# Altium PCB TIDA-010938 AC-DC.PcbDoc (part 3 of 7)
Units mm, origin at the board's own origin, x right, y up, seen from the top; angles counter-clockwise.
Board outline 275 x 170 mm, 4 copper layers (Top Layer, Layer 1, Layer 2, Bottom Layer), stack 1.787 mm thick; 711 components, 426 nets, 2196 pads, 1444 vias.
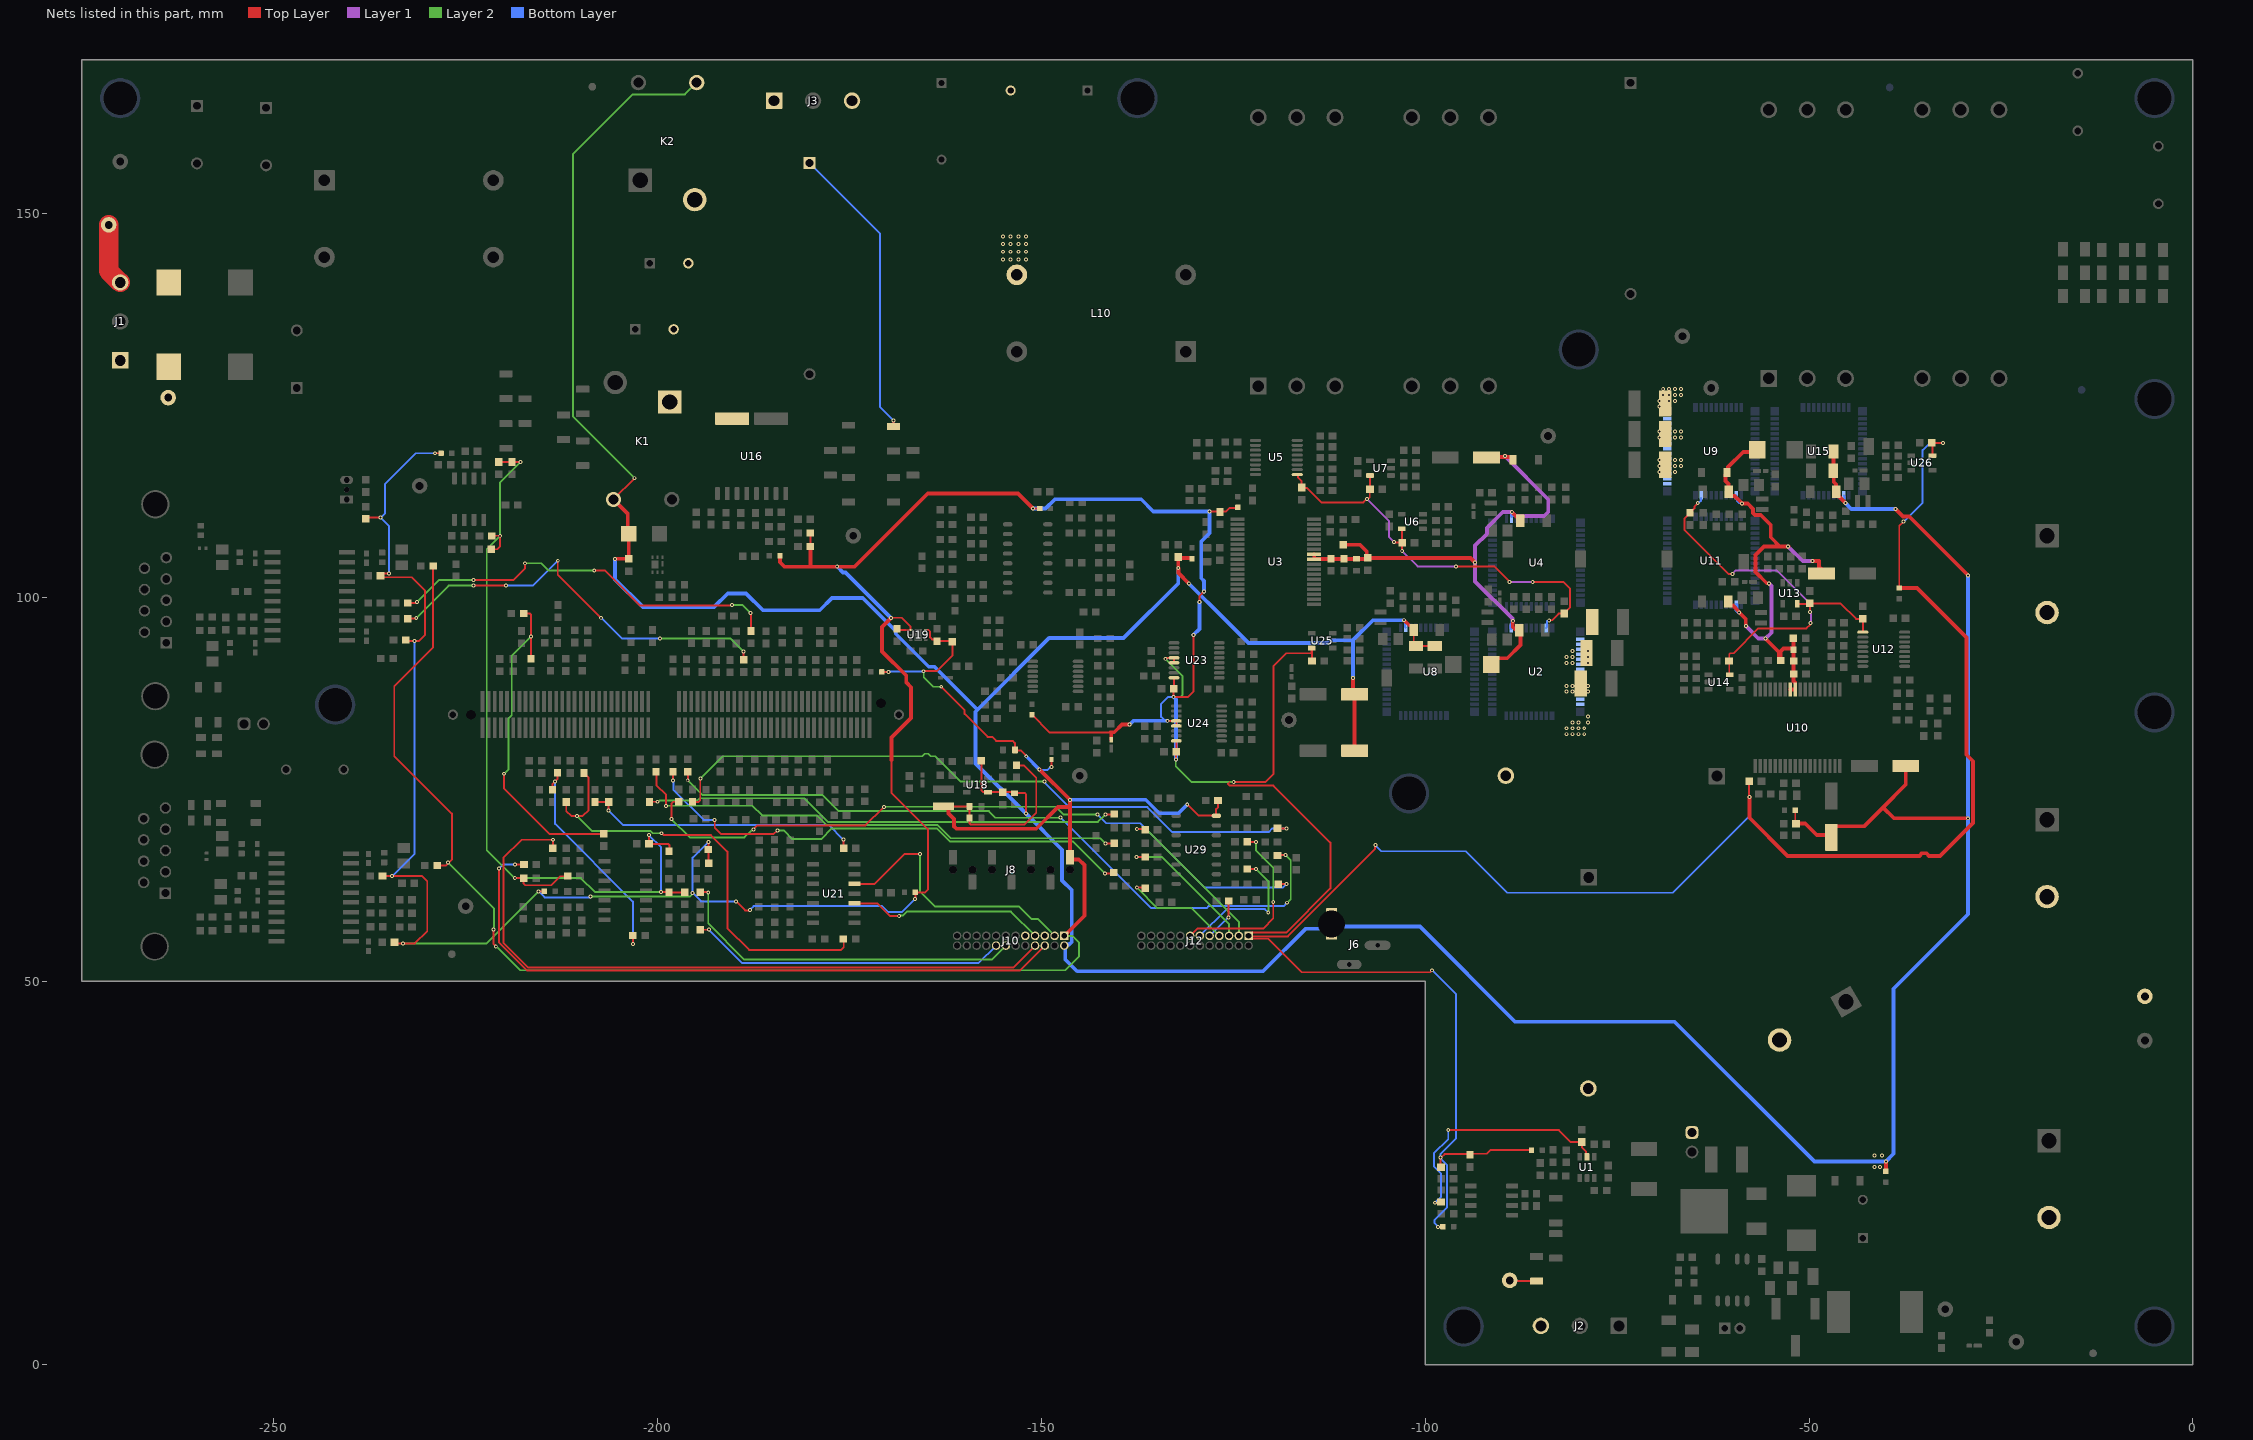
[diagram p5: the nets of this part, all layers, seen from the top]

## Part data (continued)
J6: library part CMP-0040211-1, "Power Barrel Connector Jack 2.10mm ID (0.083\"), 5.50mm OD (0.217\") Through Hole", Current_A=3A, Digikey Part Number=732-5931-ND, Manufacturer="Wurth Electronics", Mouser Part Number=710-694106402002, Operating Temperature Range="-40°C to +85°C", Voltage_V=30V
J7 J16: library part CMP-0054794-2, "Header, 2.54 mm, 2x1, Gold, TH", Color=Black, Manufacturer="Wurth Elektronik", Supplier Part Number 1=732-5315-ND
J8: library part CMP-0095208-1, "7 Position Receptacle, Bottom Entry Connector 0.100\" (2.54mm) Surface Mount Gold", Current_A=5.2A, Digikey Part Number=SSM-107-L-SV-BE-ND, Manufacturer=Samtec, Mouser Part Number=200-SSM107LSVBE, Operating Temperature Range="-55°C to +125°C", Voltage_V=572V
J10 J12: library part CMP-0003796-1, "Conn Shrouded Header (4 Sides) HDR 24 POS 1.27mm Solder ST Top Entry Thru-Hole Tube", Digikey Part Number=SHF-112-01-L-D-TH-ND, Manufacturer=Samtec, Mouser Part Number=200-SHF11201LDTH, Operating Temperature Range="-55°C to +125°C"
J11: library part CMP-0003814-2, "C2000 controlCARD-120HSEC connector, SMT", Manufacturer=Samtec
J15 J17: library part CMP-0054820-2, "Receptacle, D-Sub, 9 Position, R/A, TH", Color=Black, Current_A=3A, Manufacturer="Wurth Elektronik", Supplier Part Number 1=16T0655, Voltage_V=125V
K1 K2: library part CMP-0042926-1, "General Purpose Relay SPST-NO (1 Form A) 12VDC Coil Through Hole", Coil Power_W=450mW, Coil Resistance=320Ω, Coil Voltage_VDC=12V, Contact Rating_A=16A, Digikey Part Number=41-OJS-SH-112HEF,00000-ND, Manufacturer="TE Connectivity", Mouser Part Number=655-2071556-3, Operating Temperature Range=to
L1 L4: library part CMP-0048794-1, "Inductor 95.16 µH", Manufacturer=Bourns, Operating Temperature Range="-40°C to +125°C", Test Frequency=100Hz
L2 L3 L5 L6 L7 L9: library part CMP-0089347-1, "4.7µH Unshielded Inductor 1.1A 426mOhm Max 0806 (2016 Metric)", Digikey Part Number=2037-SDEM20161T-4R7MSCT-ND, Manufacturer=Cyntec, Operating Temperature Range="-55°C to +125°C", Test Frequency=1MHz, Tolerance_%=20%
L8 L12 L16 L17: library part CMP-0003349-2, "Ferrite Bead, 1500 ohm @ 100 MHz, 0.5 A, 0603", Manufacturer=MuRata, Supplier Part Number 1=490-5216-1-ND, Value1="0.5 ohm", Value2=0.5A, ValueDisplayed="1500 ohm"
L10 L11: library part CMP-0042320-3, "Common Mode Chokes 4mH 50mohm 250kHz", Manufacturer=Bourns, Operating Temperature Range="-40°C to +125°C", Test Frequency=250kHz
L13: library part CMP-0061866-2, "Inductor, Shielded, Ferrite, 220 uH, 2.1 A, 0.216 ohm, SMD", Manufacturer=Coilcraft, Supplier Part Number 1=994-MSS1210-224KEB, Value1="0.216 ohm", Value2=2.1A, ValueDisplayed=220uH
L14: library part CMP-0056744-1, "Inductor, Drum Core, Ferrite, 10 uH, 0.88 A, 0.276 ohm, SMD", Manufacturer=Bourns, Supplier Part Number 1=SRN3015-100MCT-ND, Value1="0.276 ohm", Value2=0.88A, ValueDisplayed=10uH
L25 L31: library part CMP-0084086-1, "100µH @ 100kHz 2 Line Common Mode Choke Surface Mount 5.8 kOhms @ 10MHz 150mA DCR 2Ohm", Digikey Part Number=445-3959-1-ND, Impedance At Frequency="5800Ω @ 10MHz", Manufacturer=TDK, Mouser Part Number=810-ACT45B1012PTL003, Operating Temperature Range="-40°C to +150°C", Test Frequency=100kHz, Tolerance_%=+50/-30%
LBL1: library part CMP-0003625-1, "Thermal Transfer Printable Labels, 0.650\" W x 0.200\" H - 10,000 per roll", Manufacturer=Brady, Supplier Part Number 1=97C5133
LOGO1: library part CMP-0074837-1, "IEC 61010-1 Hot Surface Warning"
LOGO2: library part CMP-0074835-1, "IEC 61010-1 High Voltage Warning"
Logo3: library part CMP-0074844-1
Logo5: library part CMP-0074847-1, "FCC_disclaimer"
Logo6: library part CMP-0074769-1
MP1 MP2 MP3 MP5 MP6 MP7 MP8 MP9 MP10 MP12: library part CMP-0040203-1, "Round Spacer Unthreaded Steel 0.059\" (1.50mm)", Digikey Part Number=732-7071-1-ND, Manufacturer="Wurth Electronics", Mouser Part Number=710-9774015960R, Operating Temperature Range="-55°C to +150°C"
Q1: library part CMP-0076725-1, "30-V N-Channel NexFET™ Power MOSFET", Manufacturer="Texas Instruments"
Q2: library part CMP-0001278-3, "MOSFET, N-CH, 800 V, 2.5 A, DPAK", Alternate Manufacturer=None, Manufacturer=STMicroelectronics, Supplier Part Number 1=497-7968-1-ND, Value2="19 nC"
R1: library part CMP-0084746-1, "RES, 0.001, 1%, 5 W, AEC-Q200 Grade 0, 6.35x3.05mm", Manufacturer=Bourns, Power_W=5W, TempCo="75 ppm/C", Tolerance_%=1%, Value_Code=1L000, ValueDisplayed=0.001
R2 R8 R9 R18 R19 R20 R22 R24 R25 R26 R27 R28 R29 R31 R32 R35 R37 R38 R39 R54 R56 R58 R59 R61 R62 R63 R64 R65 R66 R67 R68 R69 R71 R72 R73 R83 R86 R87 R88 R120 R121 R134 R140 R141 R150 R151 R160 R161 R169 R170 R238 R239 R257 R259 R260 R263 R264 R265 R267 R268 R269 R270 R272 R273 R274 R276 R278 R279 R281 R282 R284 R286 R311 R314 R319 R320 R323: library part CMP-0023572-3, "RES, 56, 0.1%, 0.1 W, 0603", Manufacturer="Susumu Co Ltd", Power_W=100mW, Supplier Part Number 1=RG16P56.0BCT-ND, TempCo="25 ppm/C", Tolerance_%=0.1%, Value2=0.1W, Value_Code=56R0, ValueDisplayed=56
R3 R4: library part CMP-0023661-3, "RES, 10.0, 0.1%, 0.1 W, 0603", Manufacturer="Yageo America", Power_W=100mW, TempCo="25 ppm/C", Tolerance_%=0.1%, Value2=0.1W, Value_Code=10R0, ValueDisplayed=10.0
R5 R33 R34 R50 R99 R108 R109 R110 R125 R126 R130 R131 R133 R135 R147 R149 R153 R155 R157 R158 R162 R164 R166 R167 R168 R171 R172 R173 R237 R252 R253 R254 R255 R256 R258 R297 R298 R299 R300 R301 R302 R303 R304 R305 R306 R307 R308 R310 R318 R328 R329 R330 R331 R332 R335 R336 R337 R338: library part CMP-0023404-3, "RES, 10.0 k, 0.1%, 0.1 W, 0603", Manufacturer="Susumu Co Ltd", Power_W=100mW, Supplier Part Number 1=RG16P10.0KBCT-ND, TempCo="25 ppm/C", Tolerance_%=0.1%, Value2=0.1W, Value_Code=10k0, ValueDisplayed=10.0k
R6: library part CMP-0089579-1, "SENSOR PTC 10K OHM 1% TO92S", Digikey Part Number=296-TMP6131LPGMCT-ND, Manufacturer="Texas Instruments", Max Current=400uA, Mouser Part Number=595-TMP6131LPGM, Operating Temperature Range="-40°C to +150°C", TempCo=6400ppm/°C, Tolerance_%=1%
R7 R41 R53 R55: library part CMP-0018694-3, "RES, 4.7, 5%, 0.75 W, AEC-Q200 Grade 0, 1206", Manufacturer=Vishay-Dale, Power_W=750mW, Supplier Part Number 1=541-4.7UACT-ND, TempCo="200 ppm/C", Tolerance_%=5%, Value2=0.75W, Value_Code=4R70, ValueDisplayed=4.7
R10 R30 R40 R44 R60 R74: library part CMP-0022906-5, "RES, 20.0 k, 1%, 0.1 W, 0603", Manufacturer=Yageo, Power_W=100mW, Supplier Part Number 1=311-20.0KHRCT-ND, TempCo="100 ppm/C", Tolerance_%=1%, Value2=0.1W, Value_Code=20k0, ValueDisplayed=20.0k
R11 R13 R46 R47: library part CMP-0022685-3, "RES, 12.0 k, 1%, 0.1 W, 0603", Manufacturer=Panasonic, Power_W=100mW, Supplier Part Number 1=P12.0KHCT-ND, TempCo="100 ppm/C", Tolerance_%=1%, Value2=0.1W, Value_Code=12k0, ValueDisplayed=12.0k
R12 R45: library part CMP-0025200-2, "RES, 38.8 k, 0.5%, 0.1 W, 0603", Manufacturer="Yageo America", Power_W=100mW, TempCo="50 ppm/C", Tolerance_%=0.5%, Value2=0.1W, Value_Code=38k8, ValueDisplayed=38.8k
R14 R48: library part CMP-0023076-5, "RES, 3.01 k, 1%, 0.1 W, 0603", Manufacturer=Yageo, Power_W=100mW, Supplier Part Number 1=311-3.01KHRCT-ND, TempCo="100 ppm/C", Tolerance_%=1%, Value2=0.1W, Value_Code=3k01, ValueDisplayed=3.01k
R15 R49 R84 R85 R90 R91 R104 R105: library part CMP-0023404-1, "RES, 10.0 k, 0.1%, 0.1 W, 0603", Manufacturer="Susumu Co Ltd", Power_W=100mW, Supplier Part Number 1=RG16P10.0KBCT-ND, TempCo="25 ppm/C", Tolerance_%=0.1%, Value2=0.1W, Value_Code=10k0, ValueDisplayed=10.0k
R16: library part CMP-0025771-4, "RES, 2.7 k, 5%, 0.1 W, AEC-Q200 Grade 0, 0603", Manufacturer=Vishay-Dale, Power_W=100mW, Supplier Part Number 1=541-2.7KGCT-ND, TempCo="200 ppm/C", Tolerance_%=5%, Value2=0.1W, Value_Code=2k70, ValueDisplayed=2.7k
R17 R42 R43 R51 R52 R100 R115: library part CMP-0025933-5, "RES, 5.6 k, 5%, 0.1 W, 0603", Manufacturer=Yageo, Power_W=100mW, Supplier Part Number 1=311-5.6KGRCT-ND, TempCo="100 ppm/C", Tolerance_%=5%, Value2=0.1W, Value_Code=5k60, ValueDisplayed=5.6k
R21 R23 R36: library part CMP-0018816-2, "RES, 680 k, 0.1%, 1 W, 1206", Manufacturer="Vishay Draloric", Power_W=1W, Supplier Part Number 1=541-2317-1-ND, TempCo="25 ppm/C", Tolerance_%=0.1%, Value_Code=680k
R57 R174 R175 R176 R177 R178 R179 R180 R181 R182 R183 R184 R186 R187 R188 R189 R190 R191 R192 R193 R194 R195 R196 R197 R198 R199 R200 R201 R202 R203 R204 R205 R206 R207 R208 R209 R210 R211 R212 R213 R214 R215 R216 R217 R218 R219 R220 R221 R222 R223 R224 R225 R226 R227 R228 R229 R230 R231 R232 R233 R234 R236 R240 R241 R242 R243 R244 R245 R246 R247 R248 R249 R250 R251: library part CMP-0081973-1, "RES, 0, 0%, 0.25 W, AEC-Q200 Grade 0, 0603", Manufacturer=Vishay-Dale, Power_W=250mW, Supplier Part Number 1=541-2779-1-ND, Tolerance_%=0%, Value2=0.25W, Value_Code=0
R70 R76 R102: library part CMP-0025936-5, "RES, 680, 5%, 0.1 W, 0603", Manufacturer=Yageo, Power_W=100mW, Supplier Part Number 1=311-680GRCT-ND, TempCo="100 ppm/C", Tolerance_%=5%, Value2=0.1W, Value_Code=680R, ValueDisplayed=680
R75 R114: library part CMP-0097004-1, "PTCEL Series 500 V 60 Ohm ±30 % Radial Inrush Current Limiter PTC Thermistor", Digikey Part Number=BC3317-ND, Hold Current=120mA, Manufacturer="Vishay Bccomponents", Mouser Part Number=594-PTCEL13R600LBE, Operating Temperature Range="-40°C to +105°C", Tolerance_%=30%
R77 R79 R80 R185 R235 R290 R291 R326 R327: library part CMP-0017399-3, "RES, 169 k, 1%, 0.25 W, AEC-Q200 Grade 0, 1206", Manufacturer=Panasonic, Power_W=250mW, Supplier Part Number 1=P169KFCT-ND, TempCo="100 ppm/C", Tolerance_%=1%, Value2=0.25W, Value_Code=169k
R78 R81 R82: library part CMP-0096768-1, "5 kA Varistor 1 Circuit Through Hole Disc 17mm", Clamping Voltage=730V, Digikey Part Number=118-ISOM5-275-B-L2-ND, Manufacturer=Bourns, Mouser Part Number=652-ISOM5-275-B-L2, Operating Temperature Range="-40°C to +125°C", ValueDisplayed=40pF
R89: library part CMP-0024912-2, "RES, 200, 0.5%, 0.1 W, 0603", Manufacturer="Yageo America", Power_W=100mW, TempCo="50 ppm/C", Tolerance_%=0.5%, Value2=0.1W, Value_Code=200R, ValueDisplayed=200
R92: library part CMP-0025444-3, "RES, 5.76 k, 0.5%, 0.1 W, 0603", Manufacturer="Yageo America", Power_W=100mW, TempCo="50 ppm/C", Tolerance_%=0.5%, Value2=0.1W, Value_Code=5k76, ValueDisplayed=5.76k
R93: library part CMP-0025199-3, "RES, 38.3 k, 0.5%, 0.1 W, 0603", Manufacturer="Yageo America", Power_W=100mW, TempCo="50 ppm/C", Tolerance_%=0.5%, Value2=0.1W, Value_Code=38k3, ValueDisplayed=38.3k
R94: library part CMP-0017008-3, "RES, 475 k, 1%, 0.25 W, AEC-Q200 Grade 0, 1206", Manufacturer=Vishay-Dale, Power_W=250mW, Supplier Part Number 1=541-475KFCT-ND, TempCo="100 ppm/C", Tolerance_%=1%, Value2=0.25W, Value_Code=475k
R95: library part CMP-0024711-2, "RES, 15.6 k, 0.5%, 0.1 W, 0603", Manufacturer="Yageo America", Power_W=100mW, TempCo="50 ppm/C", Tolerance_%=0.5%, Value2=0.1W, Value_Code=15k6, ValueDisplayed=15.6k
R96: library part CMP-0025116-2, "RES, 301, 0.5%, 0.1 W, 0603", Manufacturer="Yageo America", Power_W=100mW, TempCo="50 ppm/C", Tolerance_%=0.5%, Value2=0.1W, Value_Code=301R, ValueDisplayed=301
R97: library part CMP-0021844-3, "RES, 0.68, 1%, 0.125 W, AEC-Q200 Grade 0, 0805", Manufacturer=Panasonic, Power_W=125mW, Supplier Part Number 1=P.68DCT-ND, TempCo="250 ppm/C", Tolerance_%=1%, Value2=0.125W, Value_Code=R680, ValueDisplayed=0.68
R98: library part CMP-0017271-2, "RES, 0.75, 1%, 0.5 W, 1206", Manufacturer="Stackpole Electronics Inc", Power_W=500mW, Supplier Part Number 1=CSR1206FKR750CT-ND, TempCo="100 ppm/C", Tolerance_%=1%, Value2=0.5W, Value_Code=R750, ValueDisplayed=0.75
R101: library part CMP-0025877-3, "RES, 1.5 k, 5%, 0.1 W, AEC-Q200 Grade 0, 0603", Manufacturer=Panasonic, Power_W=100mW, Supplier Part Number 1=P1.5KGCT-ND, TempCo="200 ppm/C", Tolerance_%=5%, Value2=0.1W, Value_Code=1k50, ValueDisplayed=1.5k
R103: library part CMP-0023638-3, "RES, 105 k, 0.1%, 0.1 W, 0603", Manufacturer="Yageo America", Power_W=100mW, TempCo="25 ppm/C", Tolerance_%=0.1%, Value2=0.1W, Value_Code=105k
R106: library part CMP-0024922-3, "RES, 20.0 k, 0.5%, 0.1 W, 0603", Manufacturer="Yageo America", Power_W=100mW, TempCo="50 ppm/C", Tolerance_%=0.5%, Value2=0.1W, Value_Code=20k0, ValueDisplayed=20.0k
R107: library part CMP-0025733-4, "RES, 1.5 k, 5%, 0.1 W, AEC-Q200 Grade 0, 0603", Manufacturer=Vishay-Dale, Power_W=100mW, Supplier Part Number 1=541-1.5KGCT-ND, TempCo="200 ppm/C", Tolerance_%=5%, Value2=0.1W, Value_Code=1k50, ValueDisplayed=1.5k
R111 R112 R113 R116 R117 R118 R122 R123 R124 R127 R128 R129: library part CMP-0018805-2, "RES, 1.00 M, 0.1%, 1 W, 1206", Manufacturer="Vishay Draloric", Power_W=1W, Supplier Part Number 1=541-2320-1-ND, TempCo="25 ppm/C", Tolerance_%=0.1%, Value_Code=1M00, ValueDisplayed=1.00M
R132: library part CMP-0089217-1, "100 kOhms 0.25W, 1/4W Gull Wing Surface Mount Trimmer Potentiometer Cermet 12 Turn Top Adjustment", Digikey Part Number=3269W-1-104LF-ND, Manufacturer=Bourns, Mouser Part Number=652-3269W-1-104LF, Operating Temperature Range="-65°C to +150°C", Power_W=250mW, TempCo=100ppm/°C, Tolerance_%=10%
R136 R139 R143 R145 R156 R159 R163 R165: library part CMP-0024479-2, "RES, 7.32 k, 0.1%, 0.1 W, 0603", Manufacturer="Yageo America", Power_W=100mW, TempCo="25 ppm/C", Tolerance_%=0.1%, Value2=0.1W, Value_Code=7k32, ValueDisplayed=7.32k
R280 R287 R288 R289: library part CMP-0025431-3, "RES, 59.7, 0.5%, 0.1 W, 0603", Manufacturer="Yageo America", Power_W=100mW, TempCo="50 ppm/C", Tolerance_%=0.5%, Value2=0.1W, Value_Code=59R7, ValueDisplayed=59.7
R312 R316 R321 R325: library part CMP-0089632-1, "0 Ohms Jumper 0.125W, 1/8W Chip Resistor 0805 (2012 Metric) Automotive AEC-Q200 Thick Film", Digikey Part Number=RMCF0805ZT0R00CT-ND, Manufacturer="Stackpole Electronics", Operating Temperature Range="-55°C to +155°C", Power_W=125mW, TempCo=200ppm/°C
TP1 TP5 TP11 TP16 TP17 TP18 TP23: library part CMP-0003968-1, "Test Point, SMT", Manufacturer=Harwin, Supplier Part Number 1=952-2664-1-ND
TP2 TP3 TP4 TP6 TP8 TP9 TP10 TP12 TP13 TP21 TP22: library part CMP-0055138-2, "Test Point, Miniature, Black, TH", Color=Black, Manufacturer="Keystone Electronics", Supplier Part Number 1=36-5001-ND
TP7 TP19 TP20: library part CMP-0055137-2, "Test Point, Miniature, Red, TH", Color=Red, Manufacturer="Keystone Electronics", Supplier Part Number 1=36-5000-ND
TP14: library part CMP-0055164-1, "Test Point, Miniature, Green, TH", Color=Green, Manufacturer=Keystone, Supplier Part Number 1=36-5116-ND
TP15: library part CMP-0055154-1, "Test Point, Miniature, Blue, TH", Color=Blue, Manufacturer=Keystone, Supplier Part Number 1=36-5117-ND
U1: library part CMP-0013234-2, "Bidirectional, Low- and High-Side Measurement, Multichannel, Voltage Output, Current-Sense Amplifier, DBV0006A (SOT-6)", Alternate Manufacturer="Texas Instruments"
U2 U4 U8 U9 U11 U15: library part CMP-0094891-1, "650-V 30-mΩ GaN FET with Integrated Driver, Protection, and Temperature Reporting", Manufacturer="Texas Instruments", Max Supply Voltage=18V, Min Supply Voltage=7.5V, Nominal Supply Current=16mA, Operating Temperature Range="-40°C to +150°C", Output Voltage=520V
U3 U10: library part CMP-0033793-2, "Automotive 1.5-W, 12-V VIN / 12-VOUT, 15-V VIN / 15-V VOUT, HighDensity, > 5-kVRMS, Isolated DC/DC Module", Manufacturer="Texas Instruments", Max Supply Voltage=18V, Min Supply Voltage=9V, Nominal Supply Current=200-270mA, Operating Temperature Range="-40°C to +150°C", Output Voltage=10-18V, Switching Frequency=18MHz
U5 U12: library part CMP-0067607-3, "High Speed, Robust EMC, Reinforced Six-Channel Digital Isolator, DBQ0016A (SSOP-16)", Alternate Manufacturer="Texas Instruments", Alternate PartNumber=ISO7762DBQ
U6 U7 U13 U14 U25 U26: library part CMP-0051571-2, "Single 2-Input Positive-AND Gate, DBV0005A, SMALL T&R", Alternate Manufacturer="Texas Instruments", F @ Nom Voltage(Max)(Mhz)=150, Generic Part Number=SN74LVC1G08, ICC @ Nom Voltage(Max)(mA)=0.01, Operating Temperature Range(C)="-40 to 125,-40 to 85", Rating=Catalog, tpd @ Nom Voltage(Max)(ns)=4.5,6,4,5, Voltage(Nom)(V)=1.8,2.5,3.3,5
U16: library part CMP-0096052-1, Manufacturer="Texas Instruments", Operating Temperature Range=to
U17: library part CMP-0067230-2, "Constant-Voltage, Constant-Current PWM Controller with Primary-Side Regulation, D0007A (SOIC-7)", Alternate Manufacturer="Texas Instruments", Alternate PartNumber=UCC28710D
U18: library part CMP-0067067-1, "17V Input, 500mA Synchronous Step-Down Regulator in SOT-23 with Advanced Eco-Mode(TM), DBV0005A (SOT-23-5)", Alternate Manufacturer="Texas Instruments", Alternate PartNumber=TPS560200DBVT
U19: library part CMP-0013427-7, "500mA LDO, DRV0006A (WSON-6)", Alternate Manufacturer="Texas Instruments"
U20 U32: library part CMP-0097119-1, "Precision, Zero-Drift, Zero-Crossover, True Rail-to-Rail, Input/Output Operational Amplifiers", Digikey Part Number=296-OPA2388IDRCT-ND, Input Bias Current=0.00003uA, Input Offset Voltage=0.00025mV, Manufacturer="Texas Instruments", Max Dual Supply Voltage=2.75V, Max Supply Voltage=5.5V, Min Dual Supply Voltage=1.25V, Min Supply Voltage=2.5V, Mouser Part Number=595-OPA2388IDR, Nominal Supply Current=1.7-1.9mA, Operating Temperature Range="-40°C to +125°C", Output Current Per Channel=30-60mA, Voltage Gain=126-148dB
U21 U22: library part CMP-0097120-1, "Op Amp Quad Zero Drift Amplifier R-R I/O ±2.75V/5.5V 14-Pin SOIC T/R", Digikey Part Number=296-53511-1-ND, Input Bias Current=0.00003uA, Input Offset Voltage=0.00225mV, Manufacturer="Texas Instruments", Max Dual Supply Voltage=2.75V, Max Supply Voltage=5.5V, Min Dual Supply Voltage=1.25V, Min Supply Voltage=2.5V, Mouser Part Number=595-OPA4388IDR, Nominal Supply Current=1.7-1.9mA, Operating Temperature Range="-40°C to +125°C", Output Current Per Channel=60mA, Voltage Gain=148dB
U23 U24: library part CMP-0045028-1, "Data Selectors/Multiplexers With 3-State Outputs, PW0016A, TUBE", F @ Nom Voltage(Max)(Mhz)=28, Generic Part Number=SN74HC251, ICC @ Nom Voltage(Max)(mA)=0.08, Manufacturer="Texas Instruments", Operating Temperature Range(C)="-40 to 85", Rating=Catalog, tpd @ Nom Voltage(Max)(ns)=51, Voltage(Nom)(V)=3.3,5
U27: library part CMP-0066280-1, "Quadruple Bus Buffer Gate with 3-State Outputs, PW0014A (TSSOP-14)", Alternate Manufacturer="Texas Instruments", Alternate PartNumber=SN74LVC126APW
U28 U29: library part CMP-0047247-1, "Hex Buffers And Line Drivers With 3-State Outputs, D0016A, TUBE", F @ Nom Voltage(Max)(Mhz)=28, Generic Part Number=SN74HC365, ICC @ Nom Voltage(Max)(mA)=0.08, Manufacturer="Texas Instruments", Operating Temperature Range(C)="-40 to 85", Rating=Catalog, tpd @ Nom Voltage(Max)(ns)=20, Voltage(Nom)(V)=6
U30: library part CMP-0092023-2, "Reinforced 5-kVRMS Isolated CAN Transceiver with Integrated lowemissions DC-DC Converter", Manufacturer="Texas Instruments", Max Supply Voltage=5.5V, Min Supply Voltage=1.71V, Nominal Supply Current=0.3-124mA, Operating Temperature Range="-40°C to +105°C"
U31: library part CMP-0089988-1, "Reinforced 5-kVRMS Isolated RS-485/RS-422 Transceiver With Integrated Low Emissions DC-DC Converter", Manufacturer="Texas Instruments", Max Supply Voltage=5.5V, Min Supply Voltage=1.71V, Operating Temperature Range="-40°C to +105°C"
ZZ1: library part CMP-0003616-3
ZZ2: library part CMP-0077236-1
ZZ3: library part CMP-0077237-1
ZZ4: library part CMP-0077238-1

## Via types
v1: diameter 0.508, hole 0.254, Top Layer to Bottom Layer, tented both sides, 1436 vias
v2: diameter 0.508, hole 0.254, Top Layer to Bottom Layer, 6 vias
v3: diameter 0.5, hole 0.2, Top Layer to Bottom Layer, 2 vias

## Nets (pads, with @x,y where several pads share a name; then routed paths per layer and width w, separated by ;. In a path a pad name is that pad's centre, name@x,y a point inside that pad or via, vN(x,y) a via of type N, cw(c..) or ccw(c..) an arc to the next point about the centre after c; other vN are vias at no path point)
1V65_HVN: C140.2 R134.2 U1.5 | length 32
  Top Layer w0.25: v1(-98.73,21.117) -98.058,21.117 R134.2@-97.95,21.225 ; v1(-97,30.588) -82.588,30.588 -81.025,29.025 C140.2@-79.6,29.025 -79.571,28.996 -79.571,28.296 -79.051,27.776 -79.051,27.21 U1.5@-78.933,27.093
  Bottom Layer w0.25: v1(-98.73,21.117) -97.925,21.922 -97.925,24.925 -98.859,25.859 -98.859,27.541 -97,29.4 v1(-97,30.588)
1V65_REF: C45.2 C129.2 C143.1 C155.1 C165.2 R108.2 R109.2 R136.2 R156.2 R170.2 | length 107.3
  Top Layer w0.25: C45.2@-221.65,106.25 -220.9,106.25 -220.65,106.5 -220.646,106.5 -220.5,106.646 v1(-220.5,108) -221.575,108 R109.2@-221.6,107.975 ; C129.2@-220.675,117.6 R108.2@-218.95,117.6 -218.942,117.592 v1(-217.869,117.592) ; v1@-218.425,63.4 R136.2@-217.425,63.4 -217.45,63.375 -217.45,62.7 -217.225,62.475 -213.825,62.475 -212.65,63.65 C143.1@-211.775,63.65 ; v1@-201.125,68.95 -201.118,68.943 C165.2@-201.118,67.871 -198.621,67.871 -198.45,67.7 R170.2@-198.45,67.15 ; v1@-199.525,61.575 -199.52,61.58 C155.1@-198.499,61.58 -198.444,61.525 R156.2@-196.475,61.525
  Layer 2 w0.25: v1(-217.869,117.592) -220.5,114.962 v1(-220.5,108) -222.25,106.25 -222.25,67.05 v1(-218.6,63.4) -209.987,63.4 -208.187,61.6 v1@-199.6,61.6
  Bottom Layer w0.25: v1(-201.125,69) -199.546,67.421 -199.546,61.719 -199.565,61.7 v1@-199.6,61.7
  other v1: -199.575,61.6
3V3_HVN: C115.1 C123.1 C138.2 C161.2 C169.1 C176.1 C185.1 C186.1 D18.2 FB1.1 FB3.1 FB5.1 FB6.1 FB7.1 FB8.1 FB11.1 FB12.1 FB13.1 FB14.1 J12.1 L12.1 L17.1 R5.2 R11.1 R47.1 R91.1 R133.1 R166.1 R310.2 R318.2 U19.1 U23.12 U23.13 U23.16 U24.12 U24.13 U24.16 U25.5 U26.5 | length 704.3
  Top Layer w0.25: R5.2@-238,110.2 -237.825,110.375 v1(-236.075,110.375) ; R318.2@-235.842,63.678 -230.678,63.678 -230,63 -230,56.5 -231.6,54.9 L17.1@-234.3,54.9 ; v1@-235.1,103.1 -235.794,103.1 R310.2@-236.1,102.794 -235.906,102.6 -232,102.6 -230.3,100.9 -230.3,95.046 -231.046,94.3 L12.1@-232.9,94.3 ; v1(-229,118.75) FB14.1@-228.2,118.75 ; v1(-215.5,61.675) -215.488,61.687 -214.787,61.687 FB8.1@-214.75,61.65 ; R166.1@-193.381,65.394 C161.2@-193.381,67.13 ; v1(-193.375,68.125) -193.375,67.2 C161.2@-193.35,67.175 ; v1(-189.775,60.375) -188.6,59.2 v1@-188.1,59.2 ; C115.1@-180.096,106.6 R91.1@-180.096,108.373 ; v1@-169.575,97.325 -168.2,97.325 -167.035,96.16 U19.1@-167.035,95.726 -168.651,95.726 C123.1@-168.8,95.875 ; -169.54,78.813 -169.54,74.54 -164.8,69.8 -164.8,61.9 -165.146,61.554 FB7.1@-166.426,61.554 v1@-166.426,60.726 ; FB11.1@-151.217,84.665 -148.952,82.4 -141,82.4 ; v1@-151.096,111.554 -150.229,111.554 FB13.1@-150.225,111.558 ; v1(-133.85,91.975) -133.78,91.975 -133.693,92.062 -133.162,92.062 U23.12@-133.15,92.05 ; v1@-133.55,83.875 U24.12@-132.425,83.875 U24.13@-132.425,83.225 U24.13@-132.45,83.2 ; v1(-132.775,87.025) -130.875,87.025 -130.2,87.7 v1(-130.2,95.1) ; v1@-132.775,87.075 -132.775,88.05 C169.1@-132.75,88.075 ; C169.1@-132.725,88.225 U23.16@-132.725,89.5 ; U23.13@-132.725,91.425 U23.13@-132.725,91.45 U23.12@-132.725,92.1 ; v1@-132.45,78.95 -132.45,79.85 C176.1@-132.425,79.875 ; C176.1@-132.425,80.05 U24.16@-132.425,81.275 ; v1@-129.4,99.4 -129.4,100.175 v1(-128.825,100.75) ; v1(-128.125,111.175) -126.9,111.175 R11.1@-126.85,111.225 ; R11.1@-126.725,111.1 -126.661,111.164 -125.936,111.164 -125.5,111.6 -124.5,111.6 FB3.1@-124.4,111.7 ; -125.492,75.875 -125.7,75.667 -125.483,75.45 -119.775,75.45 -112.35,68.025 -112.35,62.075 -118.125,56.3 -122.58,56.3 -122.9,55.98 -122.745,55.825 -117.9,55.825 -106.549,67.176 -106.549,67.651 v1(-106.5,67.7) ; v1(-124.95,75.9) -120.85,75.9 -119.75,77 -119.75,91.05 -118.1,92.7 -114.801,92.7 -114.801,93.071 -114.75,93.02 C185.1@-114.75,91.625 ; J12.1@-122.9,55.5 -122.895,55.505 -120.48,55.505 -116.116,51.141 -99.375,51.141 -99.116,51.4 v1(-99.1,51.4) ; v1(-98.363,17.975) -98.351,17.988 -97.712,17.988 FB12.1@-97.7,18 ; R133.1@-97.95,25.75 -98,25.8 -98,26.925 v1@-97.925,27 ; v1@-97.907,27.032 -97.489,27.45 -94.25,27.45 -94.2,27.5 -92,27.5 -91.525,27.975 FB1.1@-86.15,27.975 ; v1@-57.8,73.975 R47.1@-57.8,76.025 ; FB5.1@-38.25,101.2 -38.25,109.275 v1(-37.675,109.85) ; C186.1@-34,120.1 C186.1@-33.975,120.075 ; U26.5@-33.925,118.5 -33.925,120.025 C186.1@-33.975,120.075 ; v1(-32.575,120.075) C186.1@-33.975,120.075
  Top Layer w0.5: FB6.1@-184.05,105.4 -184.05,104.55 -183.474,103.974 -180.25,103.974 ; C115.1@-180.096,106.595 -180.096,104.128 -180.25,103.974 ; v1(-169.598,97.274) -170.75,96.122 -170.75,92.929 -167.596,89.775 -167.596,88.871 -167,88.275 -167,84.25 -169.54,81.71 -169.54,78.813 ; v1(-151.1,111.55) -153.05,113.5 -164.8,113.5 -174.326,103.974 v1(-176.598,103.974) -180.25,103.974 ; D18.2@-140.9,81.42 -140.9,82.3 -141,82.4 -140.502,82.4 -139.504,83.398 -138.502,83.398 v1(-138.5,83.4) ; v1(-57.775,73.975) -57.775,71.275 -52.8,66.3 -35.625,66.3 -35.271,66.654 -34.729,66.654 -34.375,66.3 -32.95,66.3 -28.646,70.604 -28.646,78.625 -29.5,79.479 -29.5,94.75 -35.95,101.2 FB5.1@-38.25,101.2
  Layer 2 w0.25: v1@-233.1,54.9 -222.275,54.9 v1(-215.5,61.675) ; v1(-208.734,60.986) -195.814,60.986 v1@-195.4,61.4 ; v1(-133.85,91.975) -131.6,89.725 -131.6,87.3 -131.875,87.025 v1@-132.656,87.025 ; v1@-132.499,78.826 -132.499,77.999 -130.4,75.9 v1(-124.95,75.9)
  Bottom Layer w0.25: v1(-235,103.1) -235,109.3 v1(-236.075,110.375) -235.5,110.95 -235.5,114.75 -231.5,118.75 v1(-229,118.75) ; v1@-234.5,63.7 -231.675,66.525 v1@-231.675,94.225 ; v1(-215.5,61.675) -214.725,60.9 v1@-208.7,60.9 ; v1@-193.4,68.1 -195.434,66.066 v1(-195.434,61.486) -194.322,60.375 v1(-189.775,60.375) ; v1(-187.975,59.275) -187.5,59.75 -170.75,59.75 -170,59 -168.15,59 -167.4,59.75 v1(-166.475,60.675) ; -133.945,83.945 -134.4,84.4 -134.4,86.1 -133.5,87 v1@-132.8,87 ; v1(-106.5,67.7) -105.7,66.9 -94.7,66.9 -89.3,61.5 -67.75,61.5 -57.775,71.475 v1@-57.775,73.809 ; v1(-99.1,51.4) -95.971,48.271 -95.971,29.5 -98,27.471 v1(-98,27) ; v1(-98.363,17.975) -98.363,18.041 -98.775,18.453 -98.775,18.9 -97.15,20.525 -97.15,26 v1@-98.075,26.925 ; v1(-37.675,109.85) -35.2,112.325 -35.2,119.15 -34.275,120.075 v1(-32.575,120.075)
  Bottom Layer w0.5: v1(-176.598,103.974) -175.824,103.2 -175.524,103.2 v1(-169.598,97.274) ; v1(-151.1,111.55) -149.45,111.55 -148.25,112.75 -137,112.75 -135.425,111.175 v1(-128.125,111.175) -128.125,108.329 -129.179,107.275 -129.179,102.464 -128.825,102.11 v1(-128.825,100.75) ; v1(-138.5,83.4) -138,83.9 v1@-133.602,83.9 ; v1@-132.775,87.023 -132.45,86.698 v1(-132.45,78.85) ; v1(-130.2,95.1) -129.425,95.875 v1(-129.425,99.35)
  other v1: -233.175,54.875 -234.575,63.675 -133.6,83.9 -231.675,94.275
5V_HVN: C120.1 C122.1 C124.1 C126.1 C203.1 D17.2 FB9.1 J8.1 J10.1 L8.1 L14.2 L16.1 R103.1 R105.1 U19.6 U29.16 | length 272.6
  Top Layer w0.25: L8.1@-229.242,104.064 -229.242,93.458 -234.3,88.4 -234.3,79.3 -226.8,71.8 -226.8,65.8 -227.542,65.058 L16.1@-228.719,65.058 ; v1(-221.374,56.717) -221.374,54.887 -221,54.513 v1@-221,54.5 ; FB9.1@-170.81,90.264 v1@-169.861,90.264 ; v1@-165.23,90.4 -163.574,90.4 -161.6,92.374 R105.1@-161.6,94.2 -161.676,94.276 C122.1@-163.596,94.276 -163.82,94.5 -164.25,94.5 -164.5,94.75 -164.5,95.5 -164.75,95.75 -165.061,95.75 U19.6@-165.085,95.726 ; v1(-163.046,88.33) -159.998,85.283 -159.998,84.798 -157,81.8 -156.429,81.8 -155.9,81.271 -153.742,81.271 -153.455,80.983 C126.1@-153.455,80.121 ; L14.2@-162.8,72.747 L14.2@-162.766,72.781 ; L14.2@-161.89,72.755 C120.1@-159.42,72.755 ; C124.1@-159.362,71.231 -159.362,70.521 -159.215,70.375 -152.225,70.375 -150.675,71.925 -150.675,76.45 -152.325,78.1 -153.275,78.1 R103.1@-153.325,78.15 ; C124.1@-159.362,71.262 C120.1@-159.362,72.755 ; C126.1@-153.36,80.051 -152.701,80.051 v1@-152,79.35 ; v1@-148.7,78 D17.2@-148.7,78.7 ; -146.445,69.915 -146.28,70.08 ; v1(-131,73) -129.535,71.535 U29.16@-127.2,71.535 ; U29.16@-127.25,71.625 -127.25,72.4 -126.993,72.657 C203.1@-126.993,73.504 ; C203.1@-127.093,73.743 C203.1@-127.075,73.725
  Top Layer w0.5: L14.2@-161.89,72.755 -161.916,72.781 L14.2@-162.766,72.781 -162.349,72.781 -162.099,72.531 -162.099,71.824 -161.4,71.125 -161.4,70.15 -161.079,69.829 -150.671,69.829 -147.852,72.648 -146.28,72.648 ; v1(-150.275,77.575) v1(-150.275,77.575) -150.249,77.573 v1(-146.28,73.605) -146.28,72.648 ; J10.1@-147.015,55.89 -144.4,58.505 -144.4,65.098 -145.14,65.838 J8.1@-146.02,65.838 ; J8.1@-146.28,66.105 -146.28,70.08 -146.28,72.648
  Layer 2 w0.25: v1(-227.274,65.417) -221.3,59.443 v1@-221.3,56.7 ; v1@-221,54.5 -217.9,51.4 -146.9,51.4 -145.1,53.2 -145.1,55 -145.99,55.89 J10.1@-147.015,55.89 ; v1(-165.35,90.35) -165.324,90.324 -165.324,89.576 -164.078,88.33 v1(-163.046,88.33)
  Bottom Layer w0.25: v1(-169.9,90.275) -169.862,90.312 v1@-165.313,90.312 ; v1@-150.1,77.5 -149.17,77.5 -148.77,77.9 v1(-148.7,77.9)
  Bottom Layer w0.5: v1(-151.975,79.275) v1(-150.275,77.575) ; v1(-146.28,73.605) -136.414,73.605 -134.655,71.846 -132.154,71.846 v1(-131,73)
  other v1: -221.074,54.517
5V_SW1: C12.1 C39.1 C43.1 C47.1 U2.51 U5.1 U6.5 U7.5 | length 56.5
  Top Layer w0.25: U5.1@-116.675,115.978 -116.669,115.978 -116.6,115.908 -116.6,115.6 -116.1,115.1 C39.1@-116.1,114.3 -115.996,114.196 -115.396,114.196 -113.55,112.35 -108.05,112.35 v1(-107.6,112.8) ; v1@-107.525,112.725 -107.225,113.025 C47.1@-107.225,114.05 ; C47.1@-107.2,114.1 U7.5@-107.2,115.85 ; v1@-104.15,107.075 -104.1,107.125 -103.025,107.125 C43.1@-103,107.1 v2(-103,106) ; U6.5@-103.05,108.9 -103.05,107.325 C43.1@-103.025,107.3 ; v2(-96,104) -91,104 v2(-89,102) ; v2(-86,102) -82,102 -81.15,101.15 -81.15,98.65 -81.9,97.9 C12.1@-81.9,97.875 ; v1(-83.85,96.975) -83.83,96.995 -83.48,96.995 -82.625,97.85 -82.25,97.85 -82.2,97.9 C12.1@-82.1,97.9
  Layer 1 w0.25: v1(-107.6,112.8) -104.7,109.9 -104.7,107.825 v1(-104.05,107.175) ; v2(-103,106) -101,104 v2(-96,104) ; v2(-89,102) v2(-86,102)
  Bottom Layer w0.25: U2.51@-84.3,95.95 -84.154,96.096 -84.154,96.926 -83.899,96.926 v1(-83.85,96.975)
5V_SW2: C44.1 C58.1 C85.1 C91.1 U9.51 U12.1 U13.5 U14.5 | length 55.2
  Top Layer w0.25: C58.1@-65.5,111 -65.5,110.975 -66.25,110.225 -66.25,108.786 -60.464,103 v2(-60,103) ; C58.1@-65.325,111.2 -64.949,111.576 -64.949,111.8 v1(-64.504,112.245) ; U14.5@-60.4,89.818 -60.4,92.554 -60.254,92.7 -59.832,92.7 -56.607,95.925 -50.35,95.925 -49.85,96.425 v1@-49.85,96.625 ; U13.5@-51.55,99.125 C91.1@-49.9,99.125 ; v1(-49.9,98.075) C91.1@-49.9,99.125 ; C91.1@-49.9,99.2 C91.1@-49.9,99.125 ; C85.1@-43.1,97.175 -43.875,97.175 -45.875,99.175 -49.725,99.175 -49.775,99.125 C91.1@-49.9,99.125 ; U12.1@-43,95.445 C85.1@-43,97.075
  Layer 1 w0.25: v2(-60,103) -59.521,103.479 -54.179,103.479 -49.9,99.2 v1(-49.9,98.075) ; v1@-49.825,96.675 -49.825,96.722 -49.725,96.822 v1@-49.725,98.05
  Bottom Layer w0.25: v1(-64.504,112.245) -64.435,112.245 -64.141,112.538 -64.1,112.538 U9.51@-64.1,112.9
  other v1: -49.825,96.625
12V_HVN: C49.1 C94.1 C105.1 C121.1 C125.2 C238.1 C239.1 C251.1 C252.1 D13.1 FB2.1 FB4.1 FB15.2 J6.1 J10.2 K1.4 K2.4 R7.1 R13.1 R41.1 R46.1 R53.1 R55.1 R104.1 U8.44 U15.44 U18.4 | length 551.2
  Top Layer w0.25: K1.4@-205.75,112.726 -205.75,112.738 -203,115.488 v1(-203,115.5) ; R104.1@-157.825,78.7 -157.825,74.825 -157.6,74.6 U18.4@-157.3,74.6 ; U18.4@-156.958,74.599 -153.825,74.599 C121.1@-153.65,74.424 ; C121.1@-153.5,74.475 -153.487,74.488 -152.162,74.488 -152,74.325 v1(-152,71.8) ; C49.1@-101.5,95.725 -101.5,93.925 R41.1@-101.2,93.625 R7.1@-98.75,93.625 ; FB4.1@-51.8,72.25 -51.8,70.625 R46.1@-51.675,70.5
  Top Layer w0.5: K1.4@-205.75,112.726 -203.875,110.851 -203.875,108.375 D13.1@-203.75,108.25 C105.1@-203.75,105.025 ; v1@-205.425,105 C105.1@-203.75,105 ; v1(-130.8,101.8) -132.154,103.154 -132.154,103.779 v1(-132.175,103.8) -132.175,105.075 -132.125,105.125 -130.475,105.125 FB2.1@-130.375,105.025 ; v1(-109.404,89.48) -109.404,87.746 -109.5,87.65 C238.1@-109.2,87.35 -109.2,80.7 C239.1@-109.1,80.6 ; v1(-102.75,97) -102.025,96.275 -101.8,96.275 -101.75,96.225 C49.1@-101.75,95.75 ; C49.1@-101.5,95.725 C49.1@-101.2,95.425 ; R46.1@-51.675,70.5 -50.5,70.5 -49,69 C251.1@-47.1,69 ; C251.1@-47.1,68.7 C251.1@-47.1,69 ; R55.1@-47,119 -46.838,118.838 -46.838,116.488 R53.1@-46.85,116.475 ; R53.1@-46.793,115.793 -46.793,115 -46.5,114.707 -46.5,113.775 C94.1@-46.475,113.75 -46.475,113.5 v1@-45.3,112.325 ; FB15.2@-40,25.2 v1(-40,26.5) ; v1(-38.75,111.5) -37.754,110.504 -36.954,110.504 -29.303,102.853 v1@-29.304,102.852 ; C252.1@-37.4,78 -37.4,75.6 -40.375,72.625 ; v1(-29.3,71.2) -38.95,71.2 -40.375,72.625 ; C251.1@-47.1,69 -47.1,69.602 -46.55,70.152 -42.848,70.152 -40.375,72.625
  Layer 2 w0.25: v1(-203,115.5) -211,123.5 -211,157.75 -203.25,165.5 -196.43,165.5 K2.4@-194.9,167.03
  Bottom Layer w0.25: v1@-102.658,96.773 -102.658,96.125 U8.44@-102.558,96.025 ; U15.44@-45.485,113.275 -45.385,113.175 v1@-45.385,112.455
  Bottom Layer w0.5: v1(-205.525,104.975) -205.525,102.308 -201.917,98.7 -192.658,98.7 -190.858,100.5 -188.482,100.5 -186.282,98.3 -178.866,98.3 -177.266,99.9 -173.265,99.9 -168.968,95.603 -168.968,95.243 -164.671,90.946 -163.946,90.946 -158.337,85.337 ; -147.3,67 -147.3,63.1 -146.055,61.855 -146.055,55.098 -146.415,54.739 J10.2@-146.896,54.739 ; -147.3,67.1 v1(-152,71.8) -155.276,75.076 -155.326,75.076 -158.6,78.35 -158.6,85.075 -158.337,85.337 ; J10.2@-146.896,54.501 -146.896,52.821 -145.341,51.266 -121.134,51.266 -115.6,56.8 -112.65,56.8 -112.2,57.25 J6.1@-112.2,57.45 -111.85,57.1 -100.7,57.1 -88.3,44.7 -67.514,44.7 -49.314,26.5 v1(-40,26.5) -39,27.5 -39,49 -29.3,58.7 v1@-29.3,71.149 ; v1(-132.175,103.8) -132.175,101.8 -139.288,94.687 -148.987,94.687 -158.337,85.337 ; v1(-130.8,101.8) -128.329,99.329 -128.304,99.329 -127.321,98.346 -127.321,98.321 -123.017,94.017 -112.674,94.017 -112.292,94.4 -109.403,94.4 ; v1(-102.75,97) -106.803,97 -109.403,94.4 ; v1(-45.25,112.25) -44.5,111.5 v1(-38.75,111.5) ; v1(-29.3,71.2) v1(-29.3,102.85) ; v1(-109.404,89.48) v1@-109.403,89.481 ; v1@-109.403,89.481 -109.403,94.4
  other v1: -41.5,25.75 -40.75,25.75 -41.5,27.25 -40.5,27.25
12V_SW1: C11.1 C16.2 C17.2 C19.2 C20.1 C24.1 C40.1 D1.1 D2.1 R12.1 U2.44 U3.28 U3.29 U4.44 | length 75.1
  Top Layer w0.5: U3.29@-114.5,105.6 -114.475,105.6 -114.45,105.575 U3.28@-114.45,105 ; U3.28@-114.475,104.975 -112.275,104.975 -110.575,104.975 -108.975,104.975 C19.2@-107.525,104.975 ; R12.1@-110.675,106.825 -108.5,106.825 -107.625,105.95 C19.2@-107.625,105.375 ; C19.2@-107.475,105.125 -94.098,105.125 -93.502,104.529 v1(-93.5,104.529) ; C40.1@-92,117.7 -91.45,118.25 -89.737,118.25 -89.606,118.38 v1(-89.604,118.38) -89.602,118.38 -89.481,118.26 -88.745,118.26 -88.537,118.053 D2.1@-88.537,117.9 ; D1.1@-91.425,91.225 -90.599,92.051 -89.324,92.051 -87.6,93.775 -87.6,95.55 C11.1@-87.75,95.7 ; v1(-88.725,111.1) -88.15,110.525 -87.9,110.525 -87.875,110.5 C24.1@-87.875,110.025 ; v1@-88.6,96.925 -88.6,96.118 -88.307,95.825 C11.1@-87.875,95.825 ; C24.1@-87.6,109.975 C24.1@-87.5,109.875
  Layer 1 w0.5: v1(-89.604,118.38) -83.971,112.747 -83.971,111.104 -84.504,110.571 -88.19,110.571 -88.366,110.746 -88.369,110.746 v1@-88.722,111.1 ; v1(-88.725,111.1) -89.9,111.1 -91.971,109.029 -91.971,108.254 -93.5,106.725 -93.5,104.525 -93.5,102.061 -88.654,97.215 -88.654,97.006 -88.575,96.927 v1(-88.575,96.925)
  Bottom Layer w0.25: U2.44@-88.8,96.325 v1@-88.8,96.841
  Bottom Layer w0.5: U2.44@-88.8,96 U2.44@-88.8,96.325 ; U4.44@-88.74,110.55 -88.74,110.937 -88.727,110.95 -88.727,111.098 v1(-88.725,111.1)
12V_SW2: C57.1 C62.2 C63.2 C65.1 C69.1 C188.2 C240.1 D7.1 D8.1 R45.1 U9.44 U10.28 U10.29 U11.44 | length 65.6
  Top Layer w0.5: D8.1@-60.905,115.905 -60.905,115.155 -60.75,115 -60.5,114.75 -60.5,113.775 C57.1@-60.475,113.75 -60.475,113.5 -60.175,113.2 -59.703,113.2 -58.746,112.242 -58.746,112.198 v1(-58.744,112.196) ; D8.1@-60.712,116 -60.542,116.17 -60.542,116.958 -58.575,118.925 D7.1@-56.425,118.925 ; C69.1@-60.55,99.45 -60.55,99.2 -60.25,98.9 -59.925,98.9 v1@-59.125,98.1 ; v1(-59.1,98.025) -58.246,97.171 -58.246,96.246 v1(-58.225,96.225) ; v1@-58.742,112.199 -58.742,112.196 -58.741,112.195 -57.995,112.195 -57.3,111.5 -57.3,110.963 -57.037,110.7 -56.3,110.7 -55,109.4 -55,107.8 -53.811,106.611 ; v1@-55.65,94.575 -53.95,92.875 -53.95,91.975 -53.725,91.75 R45.1@-53.7,91.75 -53.7,92.925 -53.325,93.3 -52.15,93.3 -52.125,93.275 C65.1@-52.125,93.175 ; v1(-55.2,101.8) -55.221,101.821 -55.521,101.821 -57,103.3 -57,105.5 -55.889,106.611 -53.811,106.611 ; v1(-52.735,106.611) -53.811,106.611 ; v1@-52.735,106.625 v1@-52.7,106.625 ; U10.29@-52.45,87.975 U10.28@-51.825,87.975 ; C188.2@-52.05,94.65 -52.025,94.625 C65.1@-52.025,93.175 ; C62.2@-52.025,89.975 -52.025,89.05 U10.28@-51.85,88.875 ; C62.2@-52.025,90.125 C65.1@-52.025,93.15 ; v1(-49.535,104.711) -49.534,104.709 -48.693,104.709 -48.693,103.95 -48.443,103.7 C240.1@-48.4,103.7
  Layer 1 w0.5: v1(-58.225,96.225) -56.621,94.621 -55.721,94.621 v1(-55.7,94.6) -55.67,94.6 -54.9,95.37 -54.9,101.47 -55.2,101.77 v1(-55.2,101.8) ; v1(-52.735,106.611) -50.825,104.7 v1@-49.5,104.7
  Bottom Layer w0.25: U9.44@-59.485,113.275 -59.385,113.175 -59.385,112.513 -59.117,112.246 -58.794,112.246 v1(-58.744,112.196)
  Bottom Layer w0.5: U11.44@-59.485,99.025 -59.46,99 -59.46,98.313 v1@-59.197,98.05
AC_L: F1.2 J1.3 TP13.1 | length 8.1
  Top Layer w2.54: TP13.1@-271.5,148.5 -271.5,142.5 J1.3@-270,141
AC_N: F2.2 J1.1 TP15.1
ACLOAD_L: J3.1 K1.1 R75.2 U16.2
ACLOAD_N: C104.1 C106.2 J3.3 K2.3 L10.3 R114.2 R127.1 | length 38.8
  Top Layer w0.25: R127.1@-169.25,122.25 v1(-169.25,123)
  Bottom Layer w0.25: C104.1@-180.2,156.55 -171,147.35 -171,124.75 v1(-169.25,123)
  other v1: -155,144 -154,144 -153,144 -152,144 -155,145 -154,145 -153,145 -152,145 -155,146 -154,146 -153,146 -152,146 -155,147 -154,147 -153,147 -152,147
Batt_H1: R200.1 R270.1 | length 66.4
  Top Layer w0.25: v1@-198,76.1 v1(-197.975,76.125) -197.975,77.25 R200.1@-198,77.275 ; v1(-192.6,71) -192.555,70.955 -192.555,69.955 -191.771,69.171 -187.609,69.171 -187.605,69.175 -184.865,69.175 -184.44,69.6 v1(-184.4,69.6) ; v1(-141.7,64.025) -140.625,64.025 R270.1@-140.575,63.975
  Layer 2 w0.25: v1(-184.4,69.6) -183.529,69.6 -182.429,68.5 -178.673,68.5 -177.295,69.878 -163.622,69.878 -161.995,68.25 -161.945,68.2 -145.898,68.2 -141.723,64.025 v1(-141.7,64.025)
  Bottom Layer w0.25: v1(-197.975,76.125) -197.926,76.076 -197.926,74.926 -194,71 v1(-192.6,71)
Batt_H1_Buff: J12.7 R272.2 | length 14.5
  Top Layer w0.25: v1@-137.675,62.2 -137.65,62.175 v1(-137.575,62.175) -136.547,62.175 R272.2@-136.467,62.095
  Layer 2 w0.25: v1@-137.525,62.125 -134.905,59.505 -130.44,59.505 J12.7@-126.825,55.89
Batt_H2: R195.2 R278.1 | length 93.9
  Top Layer w0.25: v1@-196.1,76.1 -196.05,76.15 R195.2@-196.05,77.275 ; R278.1@-119,66.4 v1(-118.2,66.4)
  Layer 2 w0.25: v1(-196.075,76.15) -194.135,74.21 -178.51,74.21 -176.421,72.121 -156.848,72.121 -155.998,71.271 -147.629,71.271 v1@-147.6,71.3 ; v1(-118.2,66.4) -117.521,65.721 -117.521,60.679 v1(-118,60.2)
  Bottom Layer w0.25: v1(-147.5,71.3) -135.705,59.505 -128.443,59.505 -128.173,59.775 -120.709,59.775 -120.705,59.771 -118.461,59.771 -118.032,60.2 v1(-118,60.2)
Batt_H2_Buff: J12.11 R284.2 | length 17.9
  Top Layer w0.25: R284.2@-123.075,64.525 -123,64.6 v1(-122.05,64.6)
  Layer 2 w0.25: v1(-122.05,64.6) -120.425,62.975 v1@-120.425,58.95
  Bottom Layer w0.25: J12.11@-129.365,55.89 -125.88,59.375 -120.875,59.375 v1(-120.45,58.95)
Batt_L1: R201.1 R274.1 | length 91.3
  Top Layer w0.25: v1(-198.2,71.1) -198.2,73.1 -197.95,73.35 R201.1@-197.225,73.35 ; v1(-187.525,69.75) -187,70.275 -172.925,70.275 v1@-170.6,72.6 ; R274.1@-119.135,62.603 -119.113,62.625 -118.15,62.625 v1@-118.05,62.525
  Layer 2 w0.25: v1(-198.2,71.1) -195.8,68.7 -188.7,68.7 v1@-187.6,69.8 ; v1@-170.5,72.7 -148.152,72.7 -147.152,71.7 v1(-142.7,71.7)
  Bottom Layer w0.25: v1(-142.7,71.7) -141.554,70.554 -137.131,70.554 -128.773,62.196 -118.511,62.196 -118.082,62.625 v1(-118.05,62.625)
  other v1: -170.525,72.65
Batt_L1_Buff: J12.9 R279.2 | length 5.6
  Top Layer w0.25: v1(-125.625,58.3) -125.625,60.425 R279.2@-125.6,60.45
  Bottom Layer w0.25: J12.9@-128.095,55.89 -125.65,58.335 v1@-125.65,58.35
Batt_L2: R197.2 R282.1 | length 87.2
  Top Layer w0.25: R197.2@-195.479,73.321 R197.2@-195.45,73.35 -195.4,73.3 -194.7,73.3 -194.44,73.56 -194.44,76.281 -194.421,76.3 v1@-194.4,76.3 ; R282.1@-119.249,69.9 -119.225,69.875 -118.125,69.875 v1@-118.075,69.825
  Layer 2 w0.25: v1(-194.4,76.4) -191.517,79.283 -165.516,79.283 -165.194,79.604 -164.756,79.604 -164.434,79.283 -163.859,79.283 -160.577,76 v1(-149.6,76)
  Bottom Layer w0.25: v1@-149.6,75.9 -146.348,72.648 -136.2,72.648 -132.948,69.396 -120.409,69.396 -119.93,69.875 v1(-118.05,69.875)
Batt_L2_Buff: J12.13 R286.2 | length 23.7
  Top Layer w0.25: J12.13@-130.635,55.89 -129.7,56.825 -121.125,56.825 -119.8,58.15 v1(-119.8,60.3) ; R286.2@-123.075,68.125 v1(-122.05,68.125)
  Layer 2 w0.25: v1(-122.05,68.125) -122.05,67.023 -119.8,64.773 v1(-119.8,60.3)
Boost_S1: R198.1 R263.1 | length 62.2
  Top Layer w0.25: R198.1@-201.05,73.325 -201.025,73.35 -200.05,73.35 v1@-200,73.3 ; v1(-141.675,71.675) R263.1@-140.65,71.675
  Layer 2 w0.25: v1(-200,73.35) -199.93,73.35 -199.78,73.5 -194.818,73.5 -194.508,73.81 -180.91,73.81 -177.821,70.721 -142.629,70.721 -141.75,71.6 v1@-141.7,71.6
Boost_S1_Buff: J12.3 R259.2 | length 20.9
  Top Layer w0.25: v1(-137.575,69.825) -136.75,69.825 R259.2@-136.725,69.85
  Layer 2 w0.25: v1(-137.575,69.825) -136.402,69.825 -124.285,57.708 -124.285,56.06 J12.3@-124.2,55.975
Boost_S2: R199.1 R267.1 | length 65.5
  Top Layer w0.25: R199.1@-200.2,77.25 -200.15,77.2 -200.15,75.497 -198.9,74.247 v1(-198.9,72.8) ; v1@-141.7,67.9 -141.663,67.937 R267.1@-140.531,67.937
  Layer 2 w0.25: v1(-198.9,72.8) -198.871,72.829 -187.652,72.829 -186.394,71.571 -179.237,71.571 -177.987,70.321 -163.5,70.321 -161.779,68.6 -142.325,68.6 v1(-141.625,67.9)
Boost_S2_Buff: J12.5 R264.2 | length 18.1
  Top Layer w0.25: v1(-137.625,66.175) -136.7,66.175 R264.2@-136.675,66.2
  Layer 2 w0.25: v1@-137.55,66.175 -134.33,66.175 -125.555,57.4 J12.5@-125.555,55.89
CAN_RX: R213.2 R311.1 | length 53.8
  Top Layer w0.25: R311.1@-232.544,97.206 -231.406,97.206 v1@-231.4,97.2 ; v1(-224,101.5) v1(-219.75,101.5) ; v1(-213,104.75) -213,102.943 v1(-207.374,97.317) ; v1@-188.8,92.9 -188.8,91.882 R213.2@-188.782,91.864
  Layer 2 w0.25: v1(-231.434,97.286) -227.22,101.5 v1(-224,101.5) ; v1@-199.6,94.6 -199.596,94.604 -190.479,94.604 v1(-188.825,92.95)
  Bottom Layer w0.25: v1(-219.75,101.5) -216.25,101.5 v1(-213,104.75) ; v1@-207.4,97.4 -204.617,94.617 v1(-199.674,94.617)
CAN_TX: R215.2 R314.1 | length 52.3
  Top Layer w0.25: R314.1@-232.544,99.238 -231.362,99.238 v1@-231.3,99.3 ; v1(-224,102.25) -218.75,102.25 -217.274,103.726 v1(-217.274,104.417) ; v1(-208.25,103.5) -206.913,103.5 -202.334,98.921 -190.561,98.921 -190.532,98.951 -190.349,98.951 v1(-190.3,99) ; R215.2@-187.816,95.598 -187.816,97.884 v1@-187.8,97.9
  Layer 2 w0.25: v1(-231.334,99.386) -228.47,102.25 v1(-224,102.25) ; v1(-217.274,104.417) -215.167,104.417 -214.25,103.5 v1(-208.25,103.5) ; v1(-190.3,99) -188.957,99 v1(-187.874,97.917)
CS_Batt1: C146.2 R141.2 R179.2 | length 43.3
  Top Layer w0.25: v1(-220,77) -220,75.075 -216.688,71.763 -214.1,69.175 R141.2@-207.175,69.175 ; C146.2@-217.45,97.875 -216.646,97.875 -216.5,97.729 v1(-216.5,94.853) -216.5,91.978 R179.2@-216.501,91.977
  Layer 2 w0.25: v1(-220,77) -219.4,77.6 -219.4,84.205 -219,84.605 -219,92.353 v1(-216.5,94.853)
CS_Batt1+: J10.6 R139.1 | length 87
  Top Layer w0.25: v1(-220.675,64.65) -220.675,55.034 -216.991,51.35 -152.825,51.35 J10.6@-149.555,54.62 ; v1@-218.45,65.175 -218.448,65.173 R139.1@-217.397,65.173
  Bottom Layer w0.25: v1(-220.675,64.65) -220.15,65.175 v1@-218.575,65.175
  other v1: -218.55,65.175
CS_Batt1-: J10.8 R143.1 | length 91.3
  Top Layer w0.25: R143.1@-213.657,67.276 -213.6,67.333 v1@-213.6,68.275 ; v1@-213.65,68.45 -213.7,68.4 -217.725,68.4 -220.075,66.05 -220.075,55 -216.825,51.75 -153.695,51.75 J10.8@-150.825,54.62
  other v1: -213.6,68.4
CS_Batt2: C158.2 R161.2 R184.2 | length 28.7
  Top Layer w0.25: C158.2@-213.675,74.925 -213.488,74.925 C158.2@-213.449,74.886 ; C158.2@-213.675,75.3 -213.675,75.675 -213.025,76.325 R184.2@-213.025,77.125 ; R161.2@-203.226,55.933 -203.226,54.926 v1@-203.2,54.9
  Bottom Layer w0.25: v1(-213.35,75.975) -213.35,70.463 -203.225,60.337 -203.225,54.85 v1@-203.2,54.825
  other v1: -203.225,54.825
CS_Batt2+: J10.14 R159.1 | length 46.5
  Top Layer w0.25: R159.1@-194.435,61.58 -193.43,61.58 v1(-193.4,61.55)
  Layer 2 w0.25: v1@-193.425,61.525 -193.4,61.5 -193.4,57.523 -188.677,52.8 -156.455,52.8 J10.14@-154.635,54.62
CS_Batt2-: J10.16 R163.1 | length 41.3
  Top Layer w0.25: R163.1@-194.435,56.678 -193.322,56.678 v1@-193.3,56.7
  Bottom Layer w0.25: v1@-193.359,56.616 -193.241,56.616 -188.95,52.325 -158.2,52.325 J10.16@-155.905,54.62
  other v1: -193.325,56.7
CS_Boost1: C145.2 R140.2 R187.1 | length 58.9
  Top Layer w0.25: C145.2@-211.85,73.375 C145.2@-211.896,73.329 -211.896,72.146 -211.25,71.5 -209.75,71.5 -208.996,72.254 -208.996,76.487 -209.585,77.076 R187.1@-209.585,77.101 ; v1(-199.5,69.25) -199.475,69.25 -199.225,69 -193.05,69 -190.9,66.85 -190.9,56.884 -188.066,54.05 -176.075,54.05 -175.75,54.375 -175.75,55.423 R140.2@-175.801,55.474
  Layer 2 w0.25: v1(-210.5,71.5) -208.554,69.554 -200.931,69.554 -200.627,69.25 v1(-199.5,69.25)
CS_Boost1+: J10.7 U21.3 | length 25.8
  Top Layer w0.25: U21.3@-174.347,60.117 -171.397,60.117 -169.752,58.472 v1(-168.522,58.471)
  Layer 2 w0.25: v1(-168.522,58.471) -168.472,58.52 -168.055,58.52 -167.525,59.05 -153.985,59.05 J10.7@-150.825,55.89
CS_Boost1-: J10.9
CS_Boost2: C151.2 R150.2 R188.1 | length 36
  Top Layer w0.25: R188.1@-208.153,73.316 C151.2@-206.491,73.316 ; v1@-206.375,72.25 C151.2@-206.375,73.316 ; v1(-175.8,68.45) -175.8,67.55 R150.2@-175.65,67.4
  Bottom Layer w0.25: v1(-206.4,72.225) -204.475,70.3 -191.72,70.3 -191.717,70.303 -189.079,70.303 -189.076,70.3 -185.123,70.3 -177.65,70.3 -175.85,68.5 v1@-175.85,68.475
CS_Boost2+: J10.3 U21.5 | length 35
  Top Layer w0.25: U21.5@-174.347,62.657 -171.73,62.657 -167.862,66.525 v1(-165.825,66.525)
  Layer 2 w0.25: v1@-165.8,66.6 -165.825,66.575 v1(-165.825,66.525) -165.825,61.725 -163.8,59.7 -152.9,59.7 -151.3,58.1 -150.495,58.1 J10.3@-148.285,55.89
CS_Boost2-: J10.5
"DC Bus+": C2.2 C3.2 C4.2 C5.2 C30.1 C31.1 C46.1 C76.1 C88.1 C90.1 C241.2 C242.2 J2.3 J7.1 R21.1 TP7.1 TP19.1 U2.2 U2.3 U2.4 U2.5 U2.6 U2.7 U2.8 U2.9 U2.10 U2.11 U2.12 U2.13 U2.14 U2.15 U9.2 U9.3 U9.4 U9.5 U9.6 U9.7 U9.8 U9.9 U9.10 U9.11 U9.12 U9.13 U9.14 U9.15 | length 2.9
  Top Layer w0.25: TP7.1@-88.4,10.9 R21.1@-85.5,10.9
  other v1: -81.61,82.15 -80.835,82.15 -80.06,82.15 -79.285,82.15 -81.61,82.925 -80.835,82.925 -80.06,82.925 -79.285,82.925 -80.835,83.7 -80.06,83.7 -78.785,83.7 -78.785,84.45 -81.61,87.7 -80.835,87.7 -78.785,87.7 -81.61,88.45 -80.835,88.45 -78.785,88.45 -81.61,91.425 -80.835,91.425 -78.785,91.425 -81.61,92.2 -80.835,92.2 -78.785,92.2 -80.835,92.975 -78.785,92.975 -69.5,116.3 -67.45,116.3 -69.5,117.075 -67.45,117.075 -66.675,117.075 -69.5,117.85 -67.45,117.85 -66.675,117.85 -69.5,120.825 -67.45,120.825 -66.675,120.825 -69.5,121.575 -67.45,121.575 -66.675,121.575 -69.5,124.825 -69.5,125.575 -68.225,125.575 -67.45,125.575 -69,126.35 -68.225,126.35 -67.45,126.35 -66.675,126.35 -69,127.125 -68.225,127.125 -67.45,127.125 -66.675,127.125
